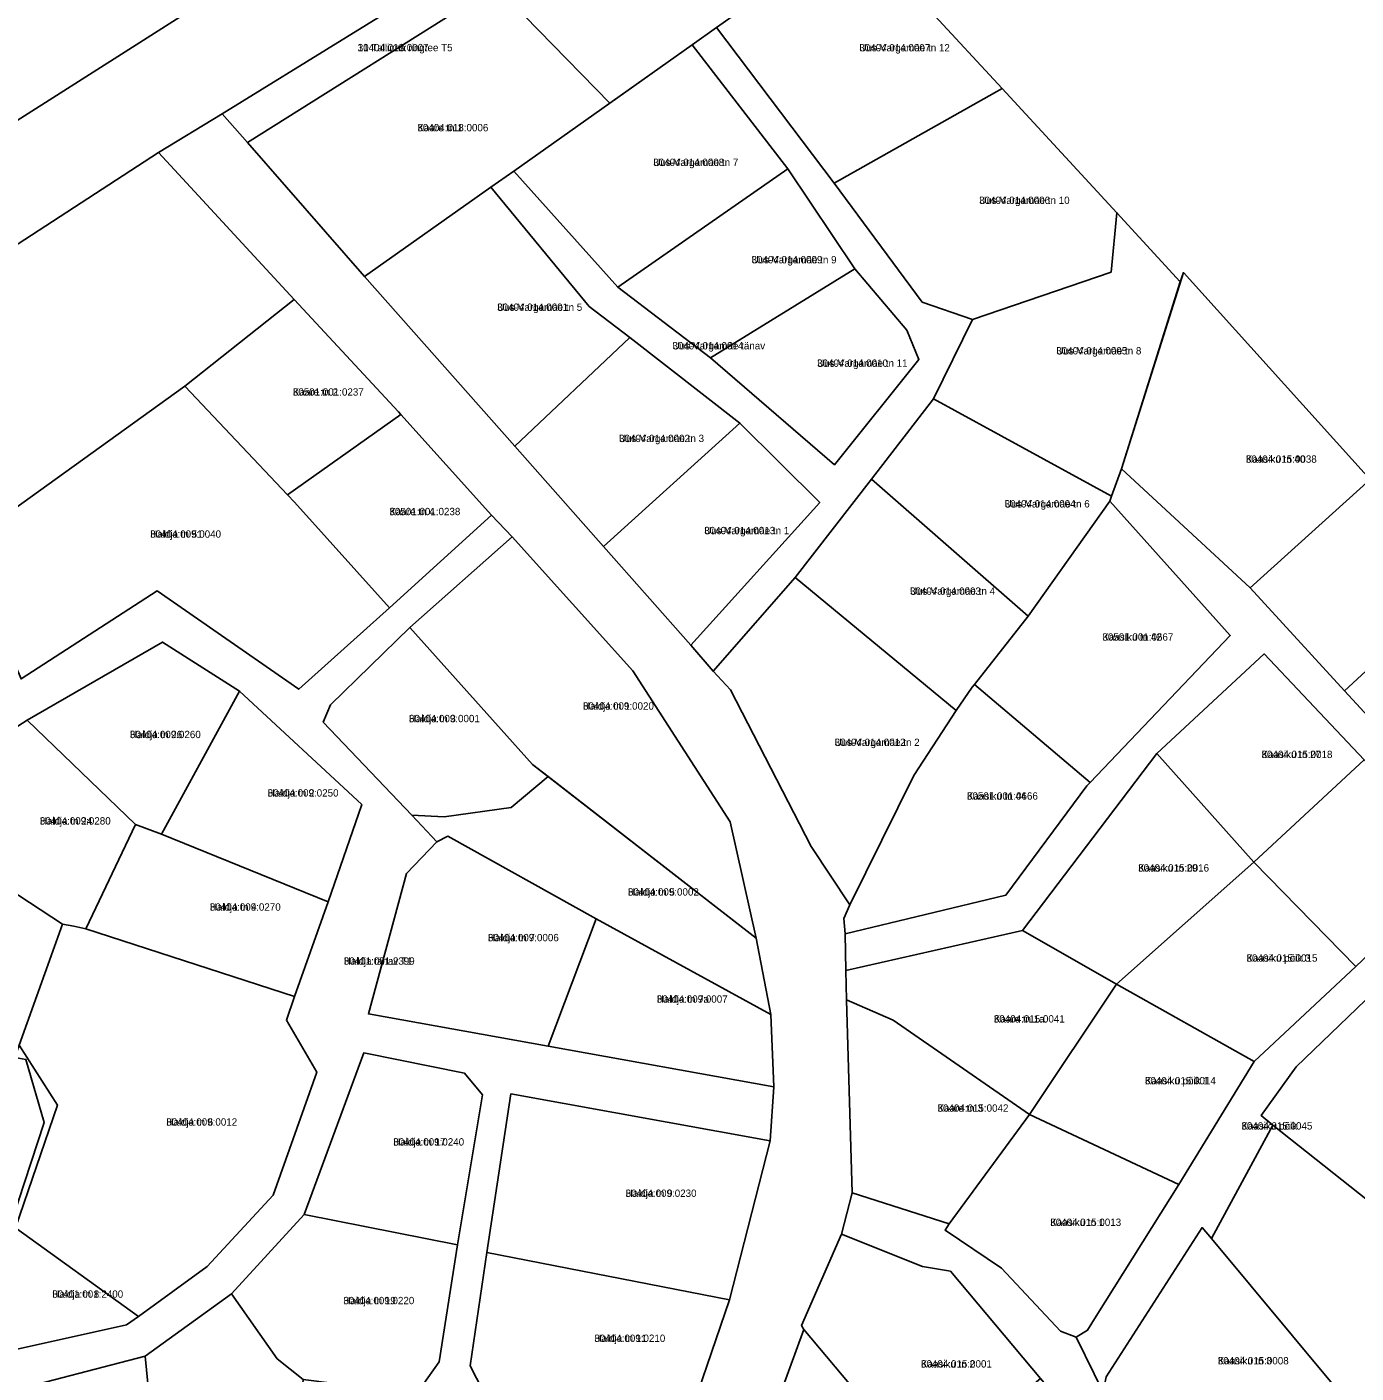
# Model space of a CAD drawing. Extents: x 542681 to 554572, y 6566489 to 6580482.
# Drawn here: x 544262.4 to 544534.3, y 6576437.8 to 6576713.2 of the extents above; entities that cross this region are included whole.
import ezdxf

# ---------------------------------------------------------------- set-up
doc = ezdxf.new("R2010")
doc.units = 0
for name, color, linetype in [('L_AADRESS', 7, 'Continuous'), ('PIIR', 7, 'Continuous'), ('TUNNUS', 7, 'Continuous')]:
    doc.layers.add(name, color=color, linetype=linetype)

msp = doc.modelspace()

# ---------------------------------------------------------------- linework, layer by layer
at = {"layer": 'PIIR'}
for points in [[(543943.88, 6576517.87), (543976.64, 6576525.41), (544022.17, 6576543.56), (544043.03, 6576556), (544047.37, 6576558.6), (544511.03, 6576853.43)], [(544511.03, 6576853.43), (544047.37, 6576558.6), (544026.62, 6576583.38), (544016.91, 6576594.91), (544014.54, 6576598.48), (544020.55, 6576597.73), (544056.47, 6576611.84), (544128.46, 6576654.95), (544137.76, 6576673.53), (544151.28, 6576682.47), (544177.78, 6576699.99), (544183.03, 6576703.47), (544209.73, 6576721.14)], [(544353.21, 6576726.8), (544302.38, 6576695.41), (544289.35, 6576687.48), (544074.8, 6576547.93), (544007.14, 6576508.85), (543946.22, 6576494.37)], [(544537.24, 6576620.61), (544499, 6576662.9), (544498.34, 6576661.01), (544485.39, 6576675.16), (544461.91, 6576700.54), (544447.29, 6576716.4)], [(544396.94, 6576425.92), (544406.15, 6576452.84), (544414.49, 6576485.36), (544415.24, 6576496.41), (544414.58, 6576511.15), (544411.58, 6576526.82), (544406.26, 6576550.6), (544386.38, 6576581.44), (544361.66, 6576608.89), (544357.45, 6576613.27), (544338.88, 6576633.89), (544338.42, 6576634.45), (544317.08, 6576657.44), (544289.35, 6576687.48), (544302.38, 6576695.41), (544307.53, 6576689.55), (544331.46, 6576662.1), (544362.21, 6576627.38), (544380.38, 6576606.87), (544398.25, 6576586.69), (544402.8, 6576581.37), (544406.37, 6576577.59), (544422.83, 6576545.51), (544430.76, 6576533.64), (544429.53, 6576530.79), (544429.79, 6576527.67), (544429.95, 6576520.16), (544430.06, 6576514.2), (544431.24, 6576474.73), (544429.03, 6576466.28), (544420.89, 6576447.56), (544421.34, 6576446.76), (544406.96, 6576407.35)], [(544535.95, 6576563.27), (544515.56, 6576584.91), (544493.57, 6576564.53), (544466.08, 6576528.39), (544429.95, 6576520.16), (544429.79, 6576527.67), (544462.69, 6576535.61), (544479.25, 6576557.96), (544479.94, 6576558.64), (544508.6, 6576588.71), (544483.95, 6576616.15), (544484.32, 6576617.18), (544486.32, 6576622.76), (544512.66, 6576598.46), (544531.99, 6576577.37), (544550.58, 6576557.21)], [(544261.23, 6576579.8), (544289.09, 6576597.81), (544318.03, 6576577.71), (544336.57, 6576594.33), (544357.45, 6576613.27), (544361.66, 6576608.89), (544340.78, 6576590.3), (544324.52, 6576574.54), (544323.03, 6576570.97), (544341.17, 6576551.92), (544346.26, 6576546.48), (544340.06, 6576540.02), (544332.29, 6576511.29), (544369.06, 6576504.7), (544415.24, 6576496.41), (544414.49, 6576485.36), (544361.44, 6576494.93), (544356.52, 6576462.51), (544353.09, 6576439.33), (544357.08, 6576431.65)], [(544262.2, 6576501.99), (544265.96, 6576489.08), (544249.95, 6576440.39), (544282.82, 6576447.7), (544285.27, 6576449.45), (544299.26, 6576459.61), (544312.79, 6576474.23), (544321.74, 6576499.42), (544315.5, 6576510.03), (544317.15, 6576514.83), (544324.04, 6576534.2), (544330.93, 6576554.14), (544305.93, 6576577.31), (544290.17, 6576587.36), (544262.49, 6576571.37), (544239.79, 6576556.86)], [(544342.09, 6576433.61), (544346.74, 6576440.15), (544350.51, 6576464.08), (544355.61, 6576494.75), (544351.95, 6576499.17), (544331.31, 6576503.32), (544319.1, 6576470.25), (544304.24, 6576454.05), (544286.61, 6576441.29), (544257.79, 6576433.83)], [(544541.75, 6576350.72), (544524.05, 6576372.36), (544505.38, 6576393.92), (544487.54, 6576415.42), (544469.74, 6576436.73), (544451.33, 6576458.67), (544445.62, 6576459.62), (544429.03, 6576466.28), (544431.24, 6576474.73), (544451.09, 6576468.39), (544450.26, 6576467.07), (544461.76, 6576459.32), (544473.86, 6576446.43), (544477.04, 6576445.17), (544482.6, 6576433.94), (544483.77, 6576431.35), (544500.83, 6576410.98), (544517.45, 6576391.19), (544543.07, 6576360.6)]]:
    msp.add_lwpolyline(points, dxfattribs=at)
for points in [[(544410.75, 6576755.06), (544431.89, 6576733.07), (544403.51, 6576713.02), (544398.5, 6576709.48), (544381.68, 6576697.59), (544358.35, 6576721.52)], [(544461.91, 6576700.54), (544427.54, 6576681.22), (544403.51, 6576713.02), (544431.89, 6576733.07), (544447.29, 6576716.4)], [(544302.38, 6576695.41), (544353.21, 6576726.8), (544358.35, 6576721.52), (544307.53, 6576689.55)], [(544307.53, 6576689.55), (544358.35, 6576721.52), (544381.68, 6576697.59), (544362, 6576683.68), (544357.3, 6576680.36), (544331.46, 6576662.1)], [(544398.25, 6576586.69), (544424.62, 6576615.89), (544408.26, 6576632.13), (544385.79, 6576649.63), (544377.47, 6576655.95), (544357.3, 6576680.36), (544362, 6576683.68), (544383.29, 6576659.94), (544402.29, 6576645.49), (544427.6, 6576623.62), (544444.91, 6576645.12), (544442.4, 6576651.14), (544431.77, 6576663.66), (544418.1, 6576684.12), (544398.5, 6576709.48), (544403.51, 6576713.02), (544427.54, 6576681.22), (544445.58, 6576656.87), (544455.87, 6576653.35), (544447.88, 6576637.06), (544435.19, 6576620.69), (544419.59, 6576600.58), (544402.8, 6576581.37)], [(544362, 6576683.68), (544398.5, 6576709.48), (544418.1, 6576684.12), (544383.29, 6576659.94)], [(544461.91, 6576700.54), (544485.39, 6576675.16), (544484.2, 6576663.01), (544455.87, 6576653.35), (544445.58, 6576656.87), (544427.54, 6576681.22)], [(544289.35, 6576687.48), (544317.08, 6576657.44), (544294.75, 6576639.67), (544249.38, 6576607.13), (544236.97, 6576636.2), (544221.4, 6576626.7), (544217.71, 6576595.47), (544216.61, 6576585.87), (544190.69, 6576571.22), (544191.83, 6576569.51), (544166.57, 6576553.56), (544141.37, 6576537.4), (544109.87, 6576517.58), (544097.38, 6576527.56), (544085.24, 6576538.48), (544074.8, 6576547.93)], [(544383.29, 6576659.94), (544418.1, 6576684.12), (544431.77, 6576663.66), (544402.29, 6576645.49)], [(544357.3, 6576680.36), (544377.47, 6576655.95), (544385.79, 6576649.63), (544362.21, 6576627.38), (544331.46, 6576662.1)], [(544455.87, 6576653.35), (544484.2, 6576663.01), (544485.39, 6576675.16), (544498.34, 6576661.01), (544486.32, 6576622.76), (544484.32, 6576617.18), (544447.88, 6576637.06)], [(544431.77, 6576663.66), (544442.4, 6576651.14), (544444.91, 6576645.12), (544427.6, 6576623.62), (544402.29, 6576645.49)], [(544499, 6576662.9), (544537.24, 6576620.61), (544512.66, 6576598.46), (544486.32, 6576622.76)], [(544294.75, 6576639.67), (544317.08, 6576657.44), (544338.42, 6576634.45), (544338.88, 6576633.89), (544315.71, 6576617.49)], [(544362.21, 6576627.38), (544385.79, 6576649.63), (544408.26, 6576632.13), (544380.38, 6576606.87)], [(544249.38, 6576607.13), (544294.75, 6576639.67), (544315.71, 6576617.49), (544317.17, 6576615.99), (544336.57, 6576594.33), (544318.03, 6576577.71), (544289.09, 6576597.81), (544261.23, 6576579.8)], [(544435.19, 6576620.69), (544447.88, 6576637.06), (544484.32, 6576617.18), (544483.95, 6576616.15), (544467.24, 6576592.67)], [(544317.17, 6576615.99), (544315.71, 6576617.49), (544338.88, 6576633.89), (544357.45, 6576613.27), (544336.57, 6576594.33)], [(544398.25, 6576586.69), (544380.38, 6576606.87), (544408.26, 6576632.13), (544424.62, 6576615.89)], [(544455.82, 6576578.12), (544452.51, 6576573.35), (544419.59, 6576600.58), (544435.19, 6576620.69), (544467.24, 6576592.67), (544456.27, 6576578.66)], [(544512.66, 6576598.46), (544537.24, 6576620.61), (544556.44, 6576599.97), (544531.99, 6576577.37)], [(544467.24, 6576592.67), (544483.95, 6576616.15), (544508.6, 6576588.71), (544479.94, 6576558.64), (544456.27, 6576578.66)], [(544340.78, 6576590.3), (544361.66, 6576608.89), (544386.38, 6576581.44), (544406.26, 6576550.6), (544411.58, 6576526.82), (544365.86, 6576562.29)], [(544402.8, 6576581.37), (544419.59, 6576600.58), (544452.51, 6576573.35), (544443.86, 6576560.08), (544430.76, 6576533.64), (544422.83, 6576545.51), (544406.37, 6576577.59)], [(544531.99, 6576577.37), (544556.44, 6576599.97), (544576.34, 6576579.97), (544550.58, 6576557.21)], [(544323.03, 6576570.97), (544324.52, 6576574.54), (544340.78, 6576590.3), (544365.86, 6576562.29), (544369.06, 6576559.86), (544361.47, 6576553.49), (544347.75, 6576551.61), (544341.17, 6576551.92)], [(544262.49, 6576571.37), (544290.17, 6576587.36), (544305.93, 6576577.31), (544289.92, 6576548.04), (544284.6, 6576550.01)], [(544493.57, 6576564.53), (544515.56, 6576584.91), (544535.95, 6576563.27), (544513.43, 6576542.36)], [(544455.82, 6576578.12), (544456.27, 6576578.66), (544479.94, 6576558.64), (544479.25, 6576557.96), (544462.69, 6576535.61), (544429.79, 6576527.67), (544429.53, 6576530.79), (544430.76, 6576533.64), (544443.86, 6576560.08), (544452.51, 6576573.35)], [(544289.92, 6576548.04), (544305.93, 6576577.31), (544330.93, 6576554.14), (544324.04, 6576534.2)], [(544239.79, 6576556.86), (544262.49, 6576571.37), (544284.6, 6576550.01), (544274.47, 6576528.68), (544272.03, 6576529.24), (544269.66, 6576529.68), (544253.97, 6576539.93)], [(544466.08, 6576528.39), (544493.57, 6576564.53), (544513.43, 6576542.36), (544485.35, 6576517.38)], [(544513.43, 6576542.36), (544535.95, 6576563.27), (544555.69, 6576541.36), (544534.27, 6576521.01)], [(544341.17, 6576551.92), (544347.75, 6576551.61), (544361.47, 6576553.49), (544369.06, 6576559.86), (544411.58, 6576526.82), (544414.58, 6576511.15), (544378.86, 6576530.77), (544348.52, 6576547.63), (544346.26, 6576546.48)], [(544274.47, 6576528.68), (544284.6, 6576550.01), (544289.92, 6576548.04), (544324.04, 6576534.2), (544317.15, 6576514.83)], [(544348.52, 6576547.63), (544378.86, 6576530.77), (544369.06, 6576504.7), (544332.29, 6576511.29), (544340.06, 6576540.02), (544346.26, 6576546.48)], [(544513.43, 6576542.36), (544534.27, 6576521.01), (544513.48, 6576501.6), (544485.35, 6576517.38)], [(544226.17, 6576511.7), (544253.97, 6576539.93), (544269.66, 6576529.68), (544260.82, 6576504.94), (544259.96, 6576502.39), (544257.69, 6576496.4), (544231.7, 6576506.88)], [(544555.69, 6576541.36), (544561.27, 6576535.5), (544538.06, 6576515.81), (544522.07, 6576500.46), (544514.92, 6576490.49), (544517.33, 6576488.57), (544504.72, 6576465.34), (544502.84, 6576467.59), (544483.23, 6576437.07), (544482.6, 6576433.94), (544477.04, 6576445.17), (544479.4, 6576446.61), (544481.19, 6576449.49), (544498.04, 6576476.42), (544513.48, 6576501.6), (544534.27, 6576521.01)], [(544269.66, 6576529.68), (544272.03, 6576529.24), (544274.47, 6576528.68), (544317.15, 6576514.83), (544315.5, 6576510.03), (544321.74, 6576499.42), (544312.79, 6576474.23), (544299.26, 6576459.61), (544285.27, 6576449.45), (544260.11, 6576467.58), (544268.65, 6576492.64), (544260.82, 6576504.94)], [(544378.86, 6576530.77), (544414.58, 6576511.15), (544415.24, 6576496.41), (544369.06, 6576504.7)], [(544430.06, 6576514.2), (544429.95, 6576520.16), (544466.08, 6576528.39), (544485.35, 6576517.38), (544467.54, 6576490.7), (544439.63, 6576510.03)], [(544485.35, 6576517.38), (544513.48, 6576501.6), (544498.04, 6576476.42), (544467.54, 6576490.7)], [(544558.85, 6576493.49), (544536.66, 6576473.22), (544517.33, 6576488.57), (544514.92, 6576490.49), (544522.07, 6576500.46), (544538.06, 6576515.81)], [(544430.06, 6576514.2), (544439.63, 6576510.03), (544467.54, 6576490.7), (544451.09, 6576468.39), (544431.24, 6576474.73)], [(544259.96, 6576502.39), (544260.82, 6576504.94), (544268.65, 6576492.64), (544260.11, 6576467.58), (544285.27, 6576449.45), (544282.82, 6576447.7), (544249.95, 6576440.39), (544265.96, 6576489.08), (544262.2, 6576501.99)], [(544319.1, 6576470.25), (544331.31, 6576503.32), (544351.95, 6576499.17), (544355.61, 6576494.75), (544350.51, 6576464.08)], [(544356.52, 6576462.51), (544361.44, 6576494.93), (544414.49, 6576485.36), (544406.15, 6576452.84)], [(544461.76, 6576459.32), (544450.26, 6576467.07), (544451.09, 6576468.39), (544467.54, 6576490.7), (544498.04, 6576476.42), (544481.19, 6576449.49), (544479.4, 6576446.61), (544477.04, 6576445.17), (544473.86, 6576446.43)], [(544536.66, 6576473.22), (544556.36, 6576450.94), (544570.95, 6576464), (544574.99, 6576458.71), (544589.57, 6576439.61), (544598.37, 6576427.81), (544595.17, 6576424.36), (544614.57, 6576393.64), (544587.01, 6576366.82), (544571.75, 6576385.09), (544546.67, 6576415.12), (544529.47, 6576435.7), (544504.72, 6576465.34), (544517.33, 6576488.57)], [(544304.24, 6576454.05), (544319.1, 6576470.25), (544350.51, 6576464.08), (544346.74, 6576440.15), (544342.09, 6576433.61), (544318.92, 6576436.54), (544313.58, 6576440.78)], [(544500.83, 6576410.98), (544483.77, 6576431.35), (544482.6, 6576433.94), (544483.23, 6576437.07), (544502.84, 6576467.59), (544504.72, 6576465.34), (544529.47, 6576435.7)], [(544429.03, 6576466.28), (544445.62, 6576459.62), (544451.33, 6576458.67), (544469.74, 6576436.73), (544446.29, 6576417.06), (544421.34, 6576446.76), (544420.89, 6576447.56)], [(544353.09, 6576439.33), (544356.52, 6576462.51), (544406.15, 6576452.84), (544396.94, 6576425.92), (544357.08, 6576431.65)], [(544291.27, 6576393.78), (544286.61, 6576441.29), (544304.24, 6576454.05), (544313.58, 6576440.78), (544318.92, 6576436.54), (544314.88, 6576394.77)], [(544446.29, 6576417.06), (544452.37, 6576409.83), (544422.48, 6576382.45), (544406.96, 6576407.35), (544421.34, 6576446.76)], [(544257.79, 6576433.83), (544286.61, 6576441.29), (544291.27, 6576393.78), (544284.48, 6576393.2), (544267.8, 6576389.6)]]:
    msp.add_lwpolyline(points, close=True, dxfattribs=at)

# ---------------------------------------------------------------- texts
at = {"layer": 'L_AADRESS'}
for s, p in [('11 Tallinna ringtee T5', (544330.09, 6576708.18)), ('Uus-Vargamäe tn 12', (544432.71, 6576708.15)), ('Kaare tn 1', (544342.31, 6576691.81)), ('Uus-Vargamäe tn 7', (544390.55, 6576684.71)), ('Uus-Vargamäe tn 10', (544457.22, 6576676.95)), ('Uus-Vargamäe tn 9', (544410.65, 6576664.8)), ('Uus-Vargamäe tn 5', (544358.62, 6576655.09)), ('Uus-Vargamäe tänav', (544394.48, 6576647.2)), ('Uus-Vargamäe tn 8', (544473.01, 6576646.17)), ('Uus-Vargamäe tn 11', (544424.07, 6576643.64)), ('Kaare tn 2', (544316.82, 6576637.75)), ('Uus-Vargamäe tn 3', (544383.55, 6576628.25)), ('Kaasiku tn 40', (544511.78, 6576624.02)), ('Uus-Vargamäe tn 6', (544462.44, 6576614.87)), ('Kaare tn 4', (544336.58, 6576613.3)), ('Uus-Vargamäe tn 1', (544400.98, 6576609.41)), ('Haldja tn 51', (544287.63, 6576608.69)), ('Uus-Vargamäe tn 4', (544443.08, 6576597.02)), ('Kaasiku tn 42', (544482.44, 6576587.64)), ('Haldja tn 1', (544376.18, 6576573.53)), ('Haldja tn 3', (544340.57, 6576570.96)), ('Haldja tn 26', (544283.48, 6576567.7)), ('Uus-Vargamäe tn 2', (544427.65, 6576566.1)), ('Kaasiku tn 27', (544514.99, 6576563.63)), ('Haldja tn 2', (544311.66, 6576555.75)), ('Kaasiku tn 44', (544454.73, 6576555.12)), ('Haldja tn 24', (544265.05, 6576550.03)), ('Kaasiku tn 29', (544489.75, 6576540.41)), ('Haldja tn 5', (544385.37, 6576535.5)), ('Haldja tn 4', (544299.83, 6576532.42)), ('Haldja tn 7', (544356.72, 6576526.16)), ('Haldja tänav T1', (544327.24, 6576521.36)), ('Kaasiku põik 3', (544511.92, 6576521.98)), ('Haldja tn 7a', (544391.27, 6576513.59)), ('Kaare tn 1a', (544460.23, 6576509.54)), ('Kaasiku põik 1', (544491.14, 6576496.9)), ('Kaare tn 3', (544448.71, 6576491.29)), ('Haldja tn 6', (544290.93, 6576488.45)), ('Kaasiku põik', (544510.88, 6576487.65)), ('Haldja tn 17', (544337.36, 6576484.38)), ('Haldja tn 9', (544384.9, 6576473.88)), ('Kaasiku tn 1', (544471.77, 6576467.94)), ('Haldja tn 8', (544267.61, 6576453.25)), ('Haldja tn 19', (544327.16, 6576451.93)), ('Haldja tn 11', (544378.51, 6576444.22)), ('Kaasiku tn 2', (544445.32, 6576438.98)), ('Kaasiku tn 3', (544506.04, 6576439.62))]:
    msp.add_text(s, height=1.5, dxfattribs=at).set_placement(p)
at = {"layer": 'TUNNUS'}
for s, p in [('30404:018:0007', (544330.09, 6576708.18)), ('30404:014:0007', (544432.71, 6576708.15)), ('30404:018:0006', (544342.31, 6576691.81)), ('30404:014:0008', (544390.55, 6576684.71)), ('30404:014:0006', (544457.22, 6576676.95)), ('30404:014:0009', (544410.65, 6576664.8)), ('30404:014:0001', (544358.62, 6576655.09)), ('30404:014:0014', (544394.48, 6576647.2)), ('30404:014:0005', (544473.01, 6576646.17)), ('30404:014:0010', (544424.07, 6576643.64)), ('30501:001:0237', (544316.82, 6576637.75)), ('30404:014:0002', (544383.55, 6576628.25)), ('30404:015:0038', (544511.78, 6576624.02)), ('30404:014:0004', (544462.44, 6576614.87)), ('30501:001:0238', (544336.58, 6576613.3)), ('30404:014:0013', (544400.98, 6576609.41)), ('30404:009:0040', (544287.63, 6576608.69)), ('30404:014:0003', (544443.08, 6576597.02)), ('30501:001:0667', (544482.44, 6576587.64)), ('30404:009:0020', (544376.18, 6576573.53)), ('30404:009:0001', (544340.57, 6576570.96)), ('30404:009:0260', (544283.48, 6576567.7)), ('30404:014:0012', (544427.65, 6576566.1)), ('30404:015:0018', (544514.99, 6576563.63)), ('30404:009:0250', (544311.66, 6576555.75)), ('30501:001:0666', (544454.73, 6576555.12)), ('30404:009:0280', (544265.05, 6576550.03)), ('30404:015:0016', (544489.75, 6576540.41)), ('30404:009:0002', (544385.37, 6576535.5)), ('30404:009:0270', (544299.83, 6576532.42)), ('30404:009:0006', (544356.72, 6576526.16)), ('30401:001:2399', (544327.24, 6576521.36)), ('30404:015:0015', (544511.92, 6576521.98)), ('30404:009:0007', (544391.27, 6576513.59)), ('30404:015:0041', (544460.23, 6576509.54)), ('30404:015:0014', (544491.14, 6576496.9)), ('30404:015:0042', (544448.71, 6576491.29)), ('30404:009:0012', (544290.93, 6576488.45)), ('30404:015:0045', (544510.88, 6576487.65)), ('30404:009:0240', (544337.36, 6576484.38)), ('30404:009:0230', (544384.9, 6576473.88)), ('30404:015:0013', (544471.77, 6576467.94)), ('30401:001:2400', (544267.61, 6576453.25)), ('30404:009:0220', (544327.16, 6576451.93)), ('30404:009:0210', (544378.51, 6576444.22)), ('30404:015:0001', (544445.32, 6576438.98)), ('30404:015:0008', (544506.04, 6576439.62))]:
    msp.add_text(s, height=1.5, dxfattribs=at).set_placement(p)

doc.saveas('drawing.dxf')
